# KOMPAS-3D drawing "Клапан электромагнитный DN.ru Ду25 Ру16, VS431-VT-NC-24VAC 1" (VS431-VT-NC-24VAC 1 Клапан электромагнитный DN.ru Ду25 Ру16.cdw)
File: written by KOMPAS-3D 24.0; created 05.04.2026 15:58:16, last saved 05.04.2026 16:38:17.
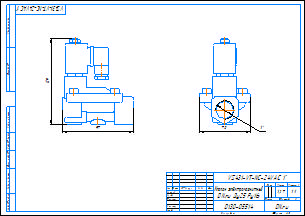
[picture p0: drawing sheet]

Document properties: c3d_UniqueCompID: ef56311e-7521-43dc-8291-0e6108b3d81d; Автор: artio; Класс точности: c; Знак неуказанной шероховатости: Шероховатость не задана; Рассекать на разрезах: Да; c3d_UniqueCompID: ef56311e-7521-43dc-8291-0e6108b3d81d; Автор: artio; Класс точности: c; Знак неуказанной шероховатости: Шероховатость не задана; Рассекать на разрезах: Да; Автор: artio; Форматы листов документа: A3; Полное имя файла: VS431-VT-NC-24VAC 1 Клапан электромагнитный DN.ru Ду25 Ру16.m3d; Масса: 1.267; Наименование: Клапан электромагнитный DN.ru Ду25 Ру16; Количество листов документа: 1; Примечание: D130-05514

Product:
- Body: Тело 1  | qty 1
    Масса: 1.729172
- Part/product: Клапан электромагнитный DN.ru Ду25 Ру16  | designation VS431-VT-NC-24VAC 1
    Масса: 1.267
    Раздел спецификации: Прочие изделия
    Примечание: D130-05514
    additional columns: ef56311e-7521-43dc-8291-0e6108b3d81d; artio; c; Шероховатость не задана; Да

Views: Вид 1, Спереди, Проекционный вид 2
Referenced files in C:\Users\artio\OneDrive\Рабочий стол\Клапан электромагнитный DN.ru\VS431\VS431-ET-NC\: VS431-ET-NC-24VAC 3-4 Клапан электромагнитный DN.ru Ду20 Ру16.m3d, VS431-ET-NC-24VAC 3-4 Клапан электромагнитный DN.ru Ду20 Ру16.cdw
Referenced files in C:\Users\artio\OneDrive\Рабочий стол\Клапан электромагнитный DN.ru\VS431\VS431-VT-NC\: VS431-VT-NC-24VAC 1 Клапан электромагнитный DN.ru Ду25 Ру16.m3d
Referenced files in C:\Users\artio\OneDrive\Рабочий стол\Клапан электромагнитный DN.ru\VS431\VS431-VT-NC\VS431-VT-NC-24VAC\Ду25\: VS431-VT-NC-24VAC 1 Клапан электромагнитный DN.ru Ду25 Ру16.m3d
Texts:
  VS431-VT-NC-24VAC 1
  Клапан электромагнитный
  DN.ru Ду25 Ру16
  VS431-VT-NC-24VAC 1"
  VS431-VT-NC-24VAC 1"-
  Клапан электромагнитный DN.ru Ду25 Ру16
  VS431-VT-NC-24VAC 1 Клапан электромагнитный DN.ru Ду25 Ру16
Dimensions and other numbers on the sheet: 0; 3; 2; 4; 70; 97; 119; 1:1; 1; 1,27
